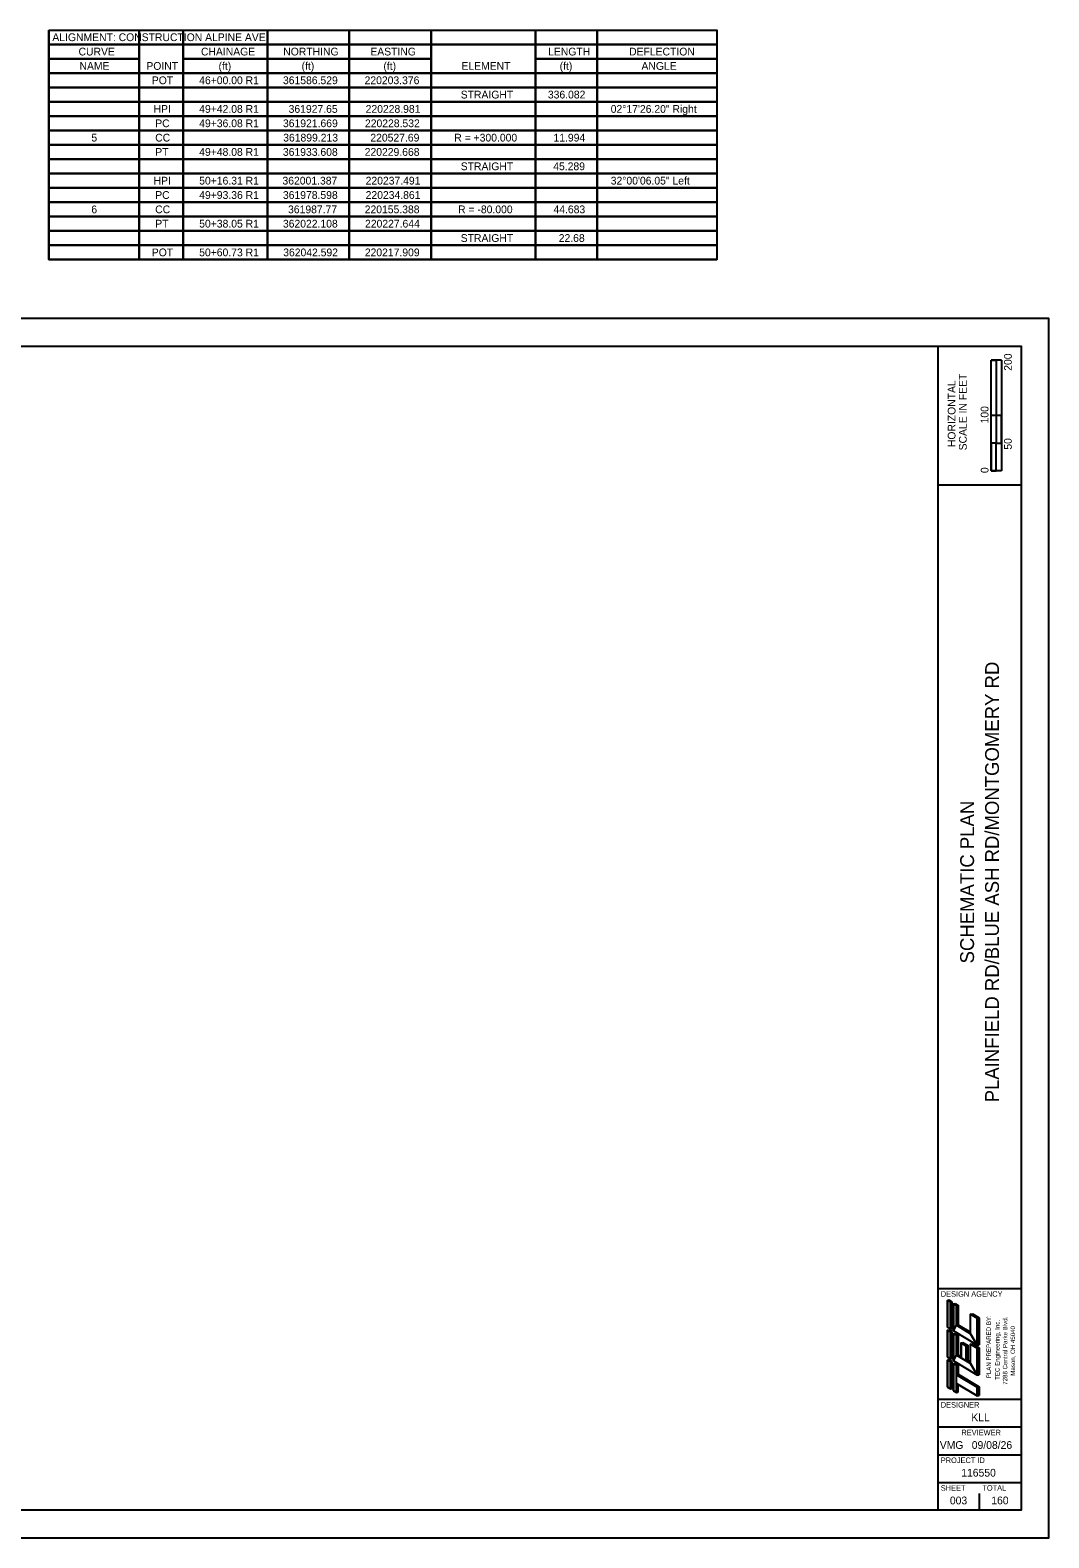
# Model space of a CAD drawing. Extents: x 1.1 to 35.1, y 0 to 27.2.
# Drawn here: x 16.71 to 35.1, y 0 to 27.2 of the extents above; entities that cross this region are included whole.
import ezdxf

# ---------------------------------------------------------------- set-up
doc = ezdxf.new("R2010")
doc.units = 0
for name, color, linetype in [('Default', 7, 'Continuous'), ('RW_X_CL_100_Bearings', 7, 'Continuous'), ('SH_Border', 7, 'Continuous'), ('SH_Cut_Line', 7, 'Continuous'), ('SH_Data', 7, 'Continuous')]:
    doc.layers.add(name, color=color, linetype=linetype)

msp = doc.modelspace()

# ---------------------------------------------------------------- linework, layer by layer
at = {"layer": 'RW_X_CL_100_Bearings'}
for p, q in [((17.053, 27.203), (29.109, 27.203)), ((17.053, 27.203), (17.053, 26.944)), ((29.109, 27.203), (29.109, 26.944)), ((17.053, 26.944), (29.109, 26.944)), ((17.053, 26.944), (17.053, 23.062)), ((18.682, 26.944), (18.682, 23.062)), ((19.473, 26.944), (19.473, 23.062)), ((20.996, 26.944), (20.996, 23.062)), ((22.472, 26.944), (22.472, 23.062)), ((23.949, 26.944), (23.949, 23.062)), ((25.836, 26.944), (25.836, 23.062)), ((26.947, 26.944), (26.947, 23.062)), ((29.109, 26.944), (29.109, 23.062)), ((17.053, 26.426), (29.109, 26.426)), ((17.053, 26.167), (29.109, 26.167)), ((17.053, 25.909), (29.109, 25.909)), ((17.053, 25.65), (29.109, 25.65)), ((17.053, 25.391), (29.109, 25.391)), ((17.053, 25.132), (29.109, 25.132)), ((17.053, 24.874), (29.109, 24.874)), ((17.053, 24.615), (29.109, 24.615)), ((17.053, 24.356), (29.109, 24.356)), ((17.053, 24.097), (29.109, 24.097)), ((17.053, 23.839), (29.109, 23.839)), ((17.053, 23.58), (29.109, 23.58)), ((17.053, 23.321), (29.109, 23.321)), ((17.053, 23.062), (29.109, 23.062)), ((33.267, 4.285), (33.299, 4.294)), ((33.267, 3.799), (33.267, 4.285)), ((33.321, 4.253), (33.267, 4.285)), ((33.353, 4.261), (33.299, 4.294)), ((33.321, 4.253), (33.353, 4.261)), ((33.321, 3.767), (33.321, 4.253)), ((33.353, 3.775), (33.353, 4.261)), ((33.375, 4.221), (33.407, 4.229)), ((33.429, 4.188), (33.375, 4.221)), ((33.375, 3.735), (33.375, 4.221)), ((33.407, 4.229), (33.461, 4.196)), ((33.429, 4.188), (33.461, 4.196)), ((33.429, 3.837), (33.429, 4.188)), ((33.461, 4.196), (33.461, 3.845)), ((33.429, 3.837), (33.461, 3.845)), ((33.686, 3.683), (33.429, 3.837)), ((33.461, 3.845), (33.686, 3.711)), ((33.686, 4.034), (33.718, 4.042)), ((33.686, 3.683), (33.686, 4.034)), ((33.807, 3.961), (33.686, 4.034)), ((33.718, 4.042), (33.839, 3.97)), ((33.807, 3.961), (33.839, 3.97)), ((33.807, 3.475), (33.807, 3.961)), ((33.839, 3.97), (33.839, 3.484)), ((33.321, 3.767), (33.267, 3.799)), ((33.267, 3.745), (33.299, 3.754)), ((33.267, 3.259), (33.267, 3.745)), ((33.321, 3.713), (33.267, 3.745)), ((33.353, 3.722), (33.299, 3.754)), ((33.321, 3.767), (33.353, 3.775)), ((33.321, 3.713), (33.353, 3.722)), ((33.321, 3.227), (33.321, 3.713)), ((33.353, 3.236), (33.353, 3.722)), ((33.807, 3.475), (33.375, 3.735)), ((33.375, 3.681), (33.407, 3.689)), ((33.375, 3.195), (33.375, 3.681)), ((33.429, 3.648), (33.375, 3.681)), ((33.407, 3.689), (33.461, 3.656)), ((33.429, 3.648), (33.461, 3.656)), ((33.429, 3.297), (33.429, 3.648)), ((33.461, 3.656), (33.461, 3.305)), ((33.429, 3.297), (33.461, 3.305)), ((33.513, 3.247), (33.429, 3.297)), ((33.461, 3.305), (33.513, 3.274)), ((33.513, 3.519), (33.546, 3.527)), ((33.513, 3.519), (33.513, 3.247)), ((33.513, 3.519), (33.601, 3.466)), ((33.546, 3.527), (33.634, 3.474)), ((33.601, 3.466), (33.634, 3.474)), ((33.601, 3.466), (33.601, 3.194)), ((33.634, 3.474), (33.634, 3.202)), ((33.686, 3.494), (33.718, 3.502)), ((33.686, 3.143), (33.686, 3.494)), ((33.807, 3.421), (33.686, 3.494)), ((33.718, 3.502), (33.839, 3.43)), ((33.807, 3.475), (33.839, 3.484)), ((33.807, 3.421), (33.839, 3.43)), ((33.807, 2.935), (33.807, 3.421)), ((33.839, 3.43), (33.839, 2.944)), ((33.321, 3.227), (33.267, 3.259)), ((33.267, 3.205), (33.299, 3.215)), ((33.267, 2.719), (33.267, 3.205)), ((33.321, 3.173), (33.267, 3.205)), ((33.353, 3.181), (33.299, 3.215)), ((33.321, 3.227), (33.353, 3.236)), ((33.321, 3.173), (33.353, 3.181)), ((33.321, 2.687), (33.321, 3.173)), ((33.353, 2.695), (33.353, 3.181)), ((33.807, 2.935), (33.375, 3.195)), ((33.375, 3.141), (33.407, 3.151)), ((33.429, 3.108), (33.375, 3.141)), ((33.375, 2.655), (33.375, 3.141)), ((33.407, 3.151), (33.461, 3.116)), ((33.429, 3.108), (33.461, 3.116)), ((33.429, 2.944), (33.429, 3.108)), ((33.461, 3.116), (33.461, 2.952)), ((33.601, 3.194), (33.634, 3.202)), ((33.686, 3.143), (33.601, 3.194)), ((33.634, 3.202), (33.686, 3.171)), ((33.429, 2.944), (33.461, 2.952)), ((33.429, 2.944), (33.807, 2.717)), ((33.429, 2.787), (33.807, 2.56)), ((33.429, 2.622), (33.429, 2.787)), ((33.461, 2.952), (33.839, 2.725)), ((33.461, 2.63), (33.461, 2.767)), ((33.807, 2.935), (33.839, 2.944)), ((33.807, 2.717), (33.839, 2.725)), ((33.839, 2.725), (33.839, 2.568)), ((33.321, 2.687), (33.267, 2.719)), ((33.321, 2.687), (33.353, 2.695)), ((33.429, 2.622), (33.375, 2.655)), ((33.429, 2.622), (33.461, 2.63)), ((33.807, 2.56), (33.807, 2.717)), ((33.807, 2.56), (33.839, 2.568))]:
    msp.add_line(p, q, dxfattribs=at)
for points in [[(17.053, 27.203), (18.682, 27.203), (18.682, 26.944), (17.053, 26.944)], [(18.682, 27.203), (19.473, 27.203), (19.473, 26.944), (18.682, 26.944)], [(19.473, 27.203), (20.996, 27.203), (20.996, 26.944), (19.473, 26.944)], [(20.996, 27.203), (22.472, 27.203), (22.472, 26.944), (20.996, 26.944)], [(22.472, 27.203), (23.949, 27.203), (23.949, 26.944), (22.472, 26.944)], [(23.949, 27.203), (25.836, 27.203), (25.836, 26.944), (23.949, 26.944)], [(25.836, 27.203), (26.947, 27.203), (26.947, 26.944), (25.836, 26.944)], [(26.947, 27.203), (29.109, 27.203), (29.109, 26.944), (26.947, 26.944)], [(17.053, 26.944), (18.682, 26.944), (18.682, 26.685), (17.053, 26.685)], [(18.682, 26.944), (19.473, 26.944), (19.473, 26.426), (18.682, 26.426)], [(19.473, 26.944), (20.996, 26.944), (20.996, 26.685), (19.473, 26.685)], [(20.996, 26.944), (22.472, 26.944), (22.472, 26.685), (20.996, 26.685)], [(22.472, 26.944), (23.949, 26.944), (23.949, 26.685), (22.472, 26.685)], [(23.949, 26.944), (25.836, 26.944), (25.836, 26.426), (23.949, 26.426)], [(25.836, 26.944), (26.947, 26.944), (26.947, 26.685), (25.836, 26.685)], [(26.947, 26.944), (29.109, 26.944), (29.109, 26.685), (26.947, 26.685)], [(17.053, 26.685), (18.682, 26.685), (18.682, 26.426), (17.053, 26.426)], [(19.473, 26.685), (20.996, 26.685), (20.996, 26.426), (19.473, 26.426)], [(20.996, 26.685), (22.472, 26.685), (22.472, 26.426), (20.996, 26.426)], [(22.472, 26.685), (23.949, 26.685), (23.949, 26.426), (22.472, 26.426)], [(25.836, 26.685), (26.947, 26.685), (26.947, 26.426), (25.836, 26.426)], [(26.947, 26.685), (29.109, 26.685), (29.109, 26.426), (26.947, 26.426)], [(17.053, 26.426), (18.682, 26.426), (18.682, 26.167), (17.053, 26.167)], [(18.682, 26.426), (19.473, 26.426), (19.473, 26.167), (18.682, 26.167)], [(19.473, 26.426), (20.996, 26.426), (20.996, 26.167), (19.473, 26.167)], [(20.996, 26.426), (22.472, 26.426), (22.472, 26.167), (20.996, 26.167)], [(22.472, 26.426), (23.949, 26.426), (23.949, 26.167), (22.472, 26.167)], [(23.949, 26.426), (25.836, 26.426), (25.836, 26.167), (23.949, 26.167)], [(25.836, 26.426), (26.947, 26.426), (26.947, 26.167), (25.836, 26.167)], [(26.947, 26.426), (29.109, 26.426), (29.109, 26.167), (26.947, 26.167)], [(17.053, 26.167), (18.682, 26.167), (18.682, 25.909), (17.053, 25.909)], [(18.682, 26.167), (19.473, 26.167), (19.473, 25.909), (18.682, 25.909)], [(19.473, 26.167), (20.996, 26.167), (20.996, 25.909), (19.473, 25.909)], [(20.996, 26.167), (22.472, 26.167), (22.472, 25.909), (20.996, 25.909)], [(22.472, 26.167), (23.949, 26.167), (23.949, 25.909), (22.472, 25.909)], [(23.949, 26.167), (25.836, 26.167), (25.836, 25.909), (23.949, 25.909)], [(25.836, 26.167), (26.947, 26.167), (26.947, 25.909), (25.836, 25.909)], [(26.947, 26.167), (29.109, 26.167), (29.109, 25.909), (26.947, 25.909)], [(17.053, 25.909), (18.682, 25.909), (18.682, 25.65), (17.053, 25.65)], [(18.682, 25.909), (19.473, 25.909), (19.473, 25.65), (18.682, 25.65)], [(19.473, 25.909), (20.996, 25.909), (20.996, 25.65), (19.473, 25.65)], [(20.996, 25.909), (22.472, 25.909), (22.472, 25.65), (20.996, 25.65)], [(22.472, 25.909), (23.949, 25.909), (23.949, 25.65), (22.472, 25.65)], [(23.949, 25.909), (25.836, 25.909), (25.836, 25.65), (23.949, 25.65)], [(25.836, 25.909), (26.947, 25.909), (26.947, 25.65), (25.836, 25.65)], [(26.947, 25.909), (29.109, 25.909), (29.109, 25.65), (26.947, 25.65)], [(17.053, 25.65), (18.682, 25.65), (18.682, 25.391), (17.053, 25.391)], [(18.682, 25.65), (19.473, 25.65), (19.473, 25.391), (18.682, 25.391)], [(19.473, 25.65), (20.996, 25.65), (20.996, 25.391), (19.473, 25.391)], [(20.996, 25.65), (22.472, 25.65), (22.472, 25.391), (20.996, 25.391)], [(22.472, 25.65), (23.949, 25.65), (23.949, 25.391), (22.472, 25.391)], [(23.949, 25.65), (25.836, 25.65), (25.836, 25.391), (23.949, 25.391)], [(25.836, 25.65), (26.947, 25.65), (26.947, 25.391), (25.836, 25.391)], [(26.947, 25.65), (29.109, 25.65), (29.109, 25.391), (26.947, 25.391)], [(17.053, 25.391), (18.682, 25.391), (18.682, 25.132), (17.053, 25.132)], [(18.682, 25.391), (19.473, 25.391), (19.473, 25.132), (18.682, 25.132)], [(19.473, 25.391), (20.996, 25.391), (20.996, 25.132), (19.473, 25.132)], [(20.996, 25.391), (22.472, 25.391), (22.472, 25.132), (20.996, 25.132)], [(22.472, 25.391), (23.949, 25.391), (23.949, 25.132), (22.472, 25.132)], [(23.949, 25.391), (25.836, 25.391), (25.836, 25.132), (23.949, 25.132)], [(25.836, 25.391), (26.947, 25.391), (26.947, 25.132), (25.836, 25.132)], [(26.947, 25.391), (29.109, 25.391), (29.109, 25.132), (26.947, 25.132)], [(17.053, 25.132), (18.682, 25.132), (18.682, 24.874), (17.053, 24.874)], [(18.682, 25.132), (19.473, 25.132), (19.473, 24.874), (18.682, 24.874)], [(19.473, 25.132), (20.996, 25.132), (20.996, 24.874), (19.473, 24.874)], [(20.996, 25.132), (22.472, 25.132), (22.472, 24.874), (20.996, 24.874)], [(22.472, 25.132), (23.949, 25.132), (23.949, 24.874), (22.472, 24.874)], [(23.949, 25.132), (25.836, 25.132), (25.836, 24.874), (23.949, 24.874)], [(25.836, 25.132), (26.947, 25.132), (26.947, 24.874), (25.836, 24.874)], [(26.947, 25.132), (29.109, 25.132), (29.109, 24.874), (26.947, 24.874)], [(17.053, 24.874), (18.682, 24.874), (18.682, 24.615), (17.053, 24.615)], [(18.682, 24.874), (19.473, 24.874), (19.473, 24.615), (18.682, 24.615)], [(19.473, 24.874), (20.996, 24.874), (20.996, 24.615), (19.473, 24.615)], [(20.996, 24.874), (22.472, 24.874), (22.472, 24.615), (20.996, 24.615)], [(22.472, 24.874), (23.949, 24.874), (23.949, 24.615), (22.472, 24.615)], [(23.949, 24.874), (25.836, 24.874), (25.836, 24.615), (23.949, 24.615)], [(25.836, 24.874), (26.947, 24.874), (26.947, 24.615), (25.836, 24.615)], [(26.947, 24.874), (29.109, 24.874), (29.109, 24.615), (26.947, 24.615)], [(17.053, 24.615), (18.682, 24.615), (18.682, 24.356), (17.053, 24.356)], [(18.682, 24.615), (19.473, 24.615), (19.473, 24.356), (18.682, 24.356)], [(19.473, 24.615), (20.996, 24.615), (20.996, 24.356), (19.473, 24.356)], [(20.996, 24.615), (22.472, 24.615), (22.472, 24.356), (20.996, 24.356)], [(22.472, 24.615), (23.949, 24.615), (23.949, 24.356), (22.472, 24.356)], [(23.949, 24.615), (25.836, 24.615), (25.836, 24.356), (23.949, 24.356)], [(25.836, 24.615), (26.947, 24.615), (26.947, 24.356), (25.836, 24.356)], [(26.947, 24.615), (29.109, 24.615), (29.109, 24.356), (26.947, 24.356)], [(17.053, 24.356), (18.682, 24.356), (18.682, 24.097), (17.053, 24.097)], [(18.682, 24.356), (19.473, 24.356), (19.473, 24.097), (18.682, 24.097)], [(19.473, 24.356), (20.996, 24.356), (20.996, 24.097), (19.473, 24.097)], [(20.996, 24.356), (22.472, 24.356), (22.472, 24.097), (20.996, 24.097)], [(22.472, 24.356), (23.949, 24.356), (23.949, 24.097), (22.472, 24.097)], [(23.949, 24.356), (25.836, 24.356), (25.836, 24.097), (23.949, 24.097)], [(25.836, 24.356), (26.947, 24.356), (26.947, 24.097), (25.836, 24.097)], [(26.947, 24.356), (29.109, 24.356), (29.109, 24.097), (26.947, 24.097)], [(17.053, 24.097), (18.682, 24.097), (18.682, 23.839), (17.053, 23.839)], [(18.682, 24.097), (19.473, 24.097), (19.473, 23.839), (18.682, 23.839)], [(19.473, 24.097), (20.996, 24.097), (20.996, 23.839), (19.473, 23.839)], [(20.996, 24.097), (22.472, 24.097), (22.472, 23.839), (20.996, 23.839)], [(22.472, 24.097), (23.949, 24.097), (23.949, 23.839), (22.472, 23.839)], [(23.949, 24.097), (25.836, 24.097), (25.836, 23.839), (23.949, 23.839)], [(25.836, 24.097), (26.947, 24.097), (26.947, 23.839), (25.836, 23.839)], [(26.947, 24.097), (29.109, 24.097), (29.109, 23.839), (26.947, 23.839)], [(17.053, 23.839), (18.682, 23.839), (18.682, 23.58), (17.053, 23.58)], [(18.682, 23.839), (19.473, 23.839), (19.473, 23.58), (18.682, 23.58)], [(19.473, 23.839), (20.996, 23.839), (20.996, 23.58), (19.473, 23.58)], [(20.996, 23.839), (22.472, 23.839), (22.472, 23.58), (20.996, 23.58)], [(22.472, 23.839), (23.949, 23.839), (23.949, 23.58), (22.472, 23.58)], [(23.949, 23.839), (25.836, 23.839), (25.836, 23.58), (23.949, 23.58)], [(25.836, 23.839), (26.947, 23.839), (26.947, 23.58), (25.836, 23.58)], [(26.947, 23.839), (29.109, 23.839), (29.109, 23.58), (26.947, 23.58)], [(17.053, 23.58), (18.682, 23.58), (18.682, 23.321), (17.053, 23.321)], [(18.682, 23.58), (19.473, 23.58), (19.473, 23.321), (18.682, 23.321)], [(19.473, 23.58), (20.996, 23.58), (20.996, 23.321), (19.473, 23.321)], [(20.996, 23.58), (22.472, 23.58), (22.472, 23.321), (20.996, 23.321)], [(22.472, 23.58), (23.949, 23.58), (23.949, 23.321), (22.472, 23.321)], [(23.949, 23.58), (25.836, 23.58), (25.836, 23.321), (23.949, 23.321)], [(25.836, 23.58), (26.947, 23.58), (26.947, 23.321), (25.836, 23.321)], [(26.947, 23.58), (29.109, 23.58), (29.109, 23.321), (26.947, 23.321)], [(17.053, 23.321), (18.682, 23.321), (18.682, 23.062), (17.053, 23.062)], [(18.682, 23.321), (19.473, 23.321), (19.473, 23.062), (18.682, 23.062)], [(19.473, 23.321), (20.996, 23.321), (20.996, 23.062), (19.473, 23.062)], [(20.996, 23.321), (22.472, 23.321), (22.472, 23.062), (20.996, 23.062)], [(22.472, 23.321), (23.949, 23.321), (23.949, 23.062), (22.472, 23.062)], [(23.949, 23.321), (25.836, 23.321), (25.836, 23.062), (23.949, 23.062)], [(25.836, 23.321), (26.947, 23.321), (26.947, 23.062), (25.836, 23.062)], [(26.947, 23.321), (29.109, 23.321), (29.109, 23.062), (26.947, 23.062)], [(33.267, 3.799), (33.321, 3.767), (33.321, 4.253), (33.267, 4.285)], [(33.375, 3.735), (33.429, 3.837), (33.429, 4.188), (33.375, 4.221)], [(33.375, 3.735), (33.429, 3.837), (33.686, 3.683), (33.807, 3.475)], [(33.807, 3.475), (33.686, 3.683), (33.686, 4.034), (33.807, 3.961)], [(33.267, 3.259), (33.321, 3.227), (33.321, 3.713), (33.267, 3.745)], [(33.375, 3.195), (33.429, 3.297), (33.429, 3.648), (33.375, 3.681)], [(33.375, 3.195), (33.429, 3.297), (33.686, 3.143), (33.807, 2.935)], [(33.513, 3.247), (33.513, 3.519), (33.601, 3.466), (33.601, 3.194)], [(33.807, 2.935), (33.686, 3.143), (33.686, 3.494), (33.807, 3.421)], [(33.267, 2.719), (33.321, 2.687), (33.321, 3.173), (33.267, 3.205)], [(33.375, 2.655), (33.429, 2.622), (33.429, 3.108), (33.375, 3.141)], [(33.429, 2.787), (33.429, 2.944), (33.807, 2.717), (33.807, 2.56)]]:
    msp.add_lwpolyline(points, close=True, dxfattribs=at)
at = {"layer": 'SH_Border'}
for p, q in [((33.098, 0.5), (33.098, 21.5)), ((33.098, 19), (34.598, 19)), ((33.098, 4.5), (34.598, 4.5)), ((33.098, 2.5), (34.598, 2.5)), ((33.098, 2), (34.598, 2)), ((33.098, 1.5), (34.598, 1.5)), ((33.098, 1), (34.598, 1))]:
    msp.add_line(p, q, dxfattribs=at)
msp.add_lwpolyline([(2.598, 21.5), (34.598, 21.5), (34.598, 0.5), (2.598, 0.5)], close=True, dxfattribs=at)
at = {"layer": 'SH_Cut_Line'}
msp.add_lwpolyline([(1.098, 0), (35.098, 0), (35.098, 22), (1.098, 22)], close=True, dxfattribs=at)
at = {"layer": 'SH_Data'}
for p, q in [((34.055, 19.25), (34.055, 21.25)), ((34.242, 21.25), (34.055, 21.25)), ((34.055, 20.25), (34.055, 21.25)), ((34.055, 21.25), (34.148, 21.25)), ((34.148, 21.25), (34.149, 21.25)), ((34.149, 21.25), (34.149, 20.25)), ((34.242, 21.25), (34.242, 19.25)), ((34.149, 20.25), (34.055, 20.25)), ((34.242, 20.25), (34.148, 20.25)), ((34.148, 20.25), (34.148, 19.75)), ((34.242, 19.75), (34.242, 20.25)), ((34.148, 19.75), (34.055, 19.75)), ((34.055, 19.75), (34.055, 19.25)), ((34.148, 19.25), (34.148, 19.75)), ((34.148, 19.75), (34.242, 19.75)), ((34.242, 19.25), (34.055, 19.25)), ((34.055, 19.25), (34.148, 19.25)), ((33.848, 3.5), (33.848, 3.5)), ((33.473, 0.675), (33.473, 0.675)), ((33.848, 0.5), (33.848, 0.8))]:
    msp.add_line(p, q, dxfattribs=at)

# ---------------------------------------------------------------- texts
at = {"layer": 'Default'}
for s, p in [('PLAN PREPARED BY:', (34.052, 2.88)), ('TEC Engineering, Inc.', (34.208, 2.851)), ('7288 Central Parke Blvd.', (34.348, 2.762)), ('Mason, OH 45040', (34.488, 2.925))]:
    msp.add_text(s, height=0.08, rotation=90, dxfattribs=at).set_placement(p)
at = {"layer": 'RW_X_CL_100_Bearings'}
for s, height, p in [('ALIGNMENT: CONSTRUCTION ALPINE AVE', 0.14004, (17.114, 27.005)), ('CURVE', 0.14, (17.587, 26.746)), ('CHAINAGE', 0.14, (19.796, 26.746)), ('NORTHING', 0.14, (21.281, 26.746)), ('EASTING', 0.14, (22.853, 26.746)), ('LENGTH', 0.14, (26.061, 26.746)), ('DEFLECTION', 0.14, (27.523, 26.746)), ('NAME', 0.14, (17.604, 26.487)), ('POINT', 0.14, (18.811, 26.487)), ('(ft)', 0.14, (20.113, 26.487)), ('(ft)', 0.14, (21.612, 26.487)), ('(ft)', 0.14, (23.089, 26.487)), ('ELEMENT', 0.14, (24.497, 26.487)), ('(ft)', 0.14, (26.27, 26.487)), ('ANGLE', 0.14, (27.746, 26.487)), ('POT', 0.14, (18.909, 26.228)), ('46+00.00 R1', 0.14004, (19.764, 26.228)), ('361586.529', 0.14, (21.276, 26.228)), ('220203.376', 0.14, (22.749, 26.228)), ('HPI', 0.14, (18.94, 25.711)), ('49+42.08 R1', 0.14004, (19.764, 25.711)), ('361927.65', 0.14, (21.378, 25.711)), ('220228.981', 0.14, (22.768, 25.711)), ('STRAIGHT', 0.14, (24.484, 25.97)), ('336.082', 0.14, (26.057, 25.97)), ('02°17\'26.20" Right', 0.14004, (27.191, 25.711)), ('PC', 0.14, (18.971, 25.452)), ('49+36.08 R1', 0.14004, (19.764, 25.452)), ('361921.669', 0.14, (21.276, 25.452)), ('220228.532', 0.14, (22.756, 25.452)), ('5', 0.14, (17.819, 25.193)), ('CC', 0.14, (18.97, 25.193)), ('361899.213', 0.14, (21.28, 25.193)), ('220527.69', 0.14, (22.853, 25.193)), ('R = +300.000', 0.14004, (24.368, 25.193)), ('11.994', 0.14, (26.158, 25.193)), ('PT', 0.14, (18.971, 24.935)), ('49+48.08 R1', 0.14004, (19.764, 24.935)), ('361933.608', 0.14, (21.275, 24.935)), ('220229.668', 0.14, (22.751, 24.935)), ('STRAIGHT', 0.14, (24.484, 24.676)), ('45.289', 0.14, (26.154, 24.676)), ('HPI', 0.14, (18.94, 24.417)), ('50+16.31 R1', 0.14004, (19.764, 24.417)), ('362001.387', 0.14, (21.267, 24.417)), ('220237.491', 0.14, (22.768, 24.417)), ('32°00\'06.05" Left', 0.14004, (27.191, 24.417)), ('PC', 0.14, (18.971, 24.158)), ('49+93.36 R1', 0.14004, (19.764, 24.158)), ('361978.598', 0.14, (21.275, 24.158)), ('220234.861', 0.14, (22.768, 24.158)), ('6', 0.14, (17.817, 23.899)), ('CC', 0.14, (18.97, 23.899)), ('361987.77', 0.14, (21.368, 23.899)), ('220155.388', 0.14, (22.751, 23.899)), ('R = -80.000', 0.14004, (24.437, 23.899)), ('44.683', 0.14, (26.158, 23.899)), ('PT', 0.14, (18.971, 23.641)), ('50+38.05 R1', 0.14004, (19.764, 23.641)), ('362022.108', 0.14, (21.275, 23.641)), ('220227.644', 0.14, (22.757, 23.641)), ('STRAIGHT', 0.14, (24.484, 23.382)), ('22.68', 0.14, (26.253, 23.382)), ('POT', 0.14, (18.909, 23.123)), ('50+60.73 R1', 0.14004, (19.764, 23.123)), ('362042.592', 0.14, (21.28, 23.123)), ('220217.909', 0.14, (22.753, 23.123))]:
    msp.add_text(s, height=height, dxfattribs=at).set_placement(p)
at = {"layer": 'SH_Data'}
for s, height, p in [('200', 0.14, (34.429, 21.057)), ('SCALE IN FEET', 0.14, (33.616, 19.621)), ('HORIZONTAL', 0.14, (33.413, 19.679)), ('100', 0.14, (34.009, 20.107)), ('50', 0.14, (34.429, 19.633)), ('0', 0.14, (34.009, 19.211)), ('PLAINFIELD RD/BLUE ASH RD/MONTGOMERY RD', 0.25, (34.198, 7.858)), ('SCHEMATIC PLAN', 0.25, (33.748, 10.364))]:
    msp.add_text(s, height=height, rotation=90, dxfattribs=at).set_placement(p)
for s, height, p in [('DESIGN AGENCY', 0.1, (33.148, 4.35)), ('DESIGNER', 0.1, (33.148, 2.35)), ('KLL', 0.14, (33.699, 2.105)), ('REVIEWER', 0.1, (33.52, 1.85)), ('VMG', 0.14, (33.13, 1.605)), ('09/08/26', 0.14, (33.707, 1.605)), ('PROJECT ID', 0.1, (33.148, 1.35)), ('116550', 0.14, (33.517, 1.105)), ('SHEET', 0.1, (33.148, 0.85)), ('TOTAL', 0.1, (33.898, 0.85)), ('003', 0.14, (33.312, 0.605)), ('160', 0.14, (34.059, 0.605))]:
    msp.add_text(s, height=height, dxfattribs=at).set_placement(p)

doc.saveas('drawing.dxf')
